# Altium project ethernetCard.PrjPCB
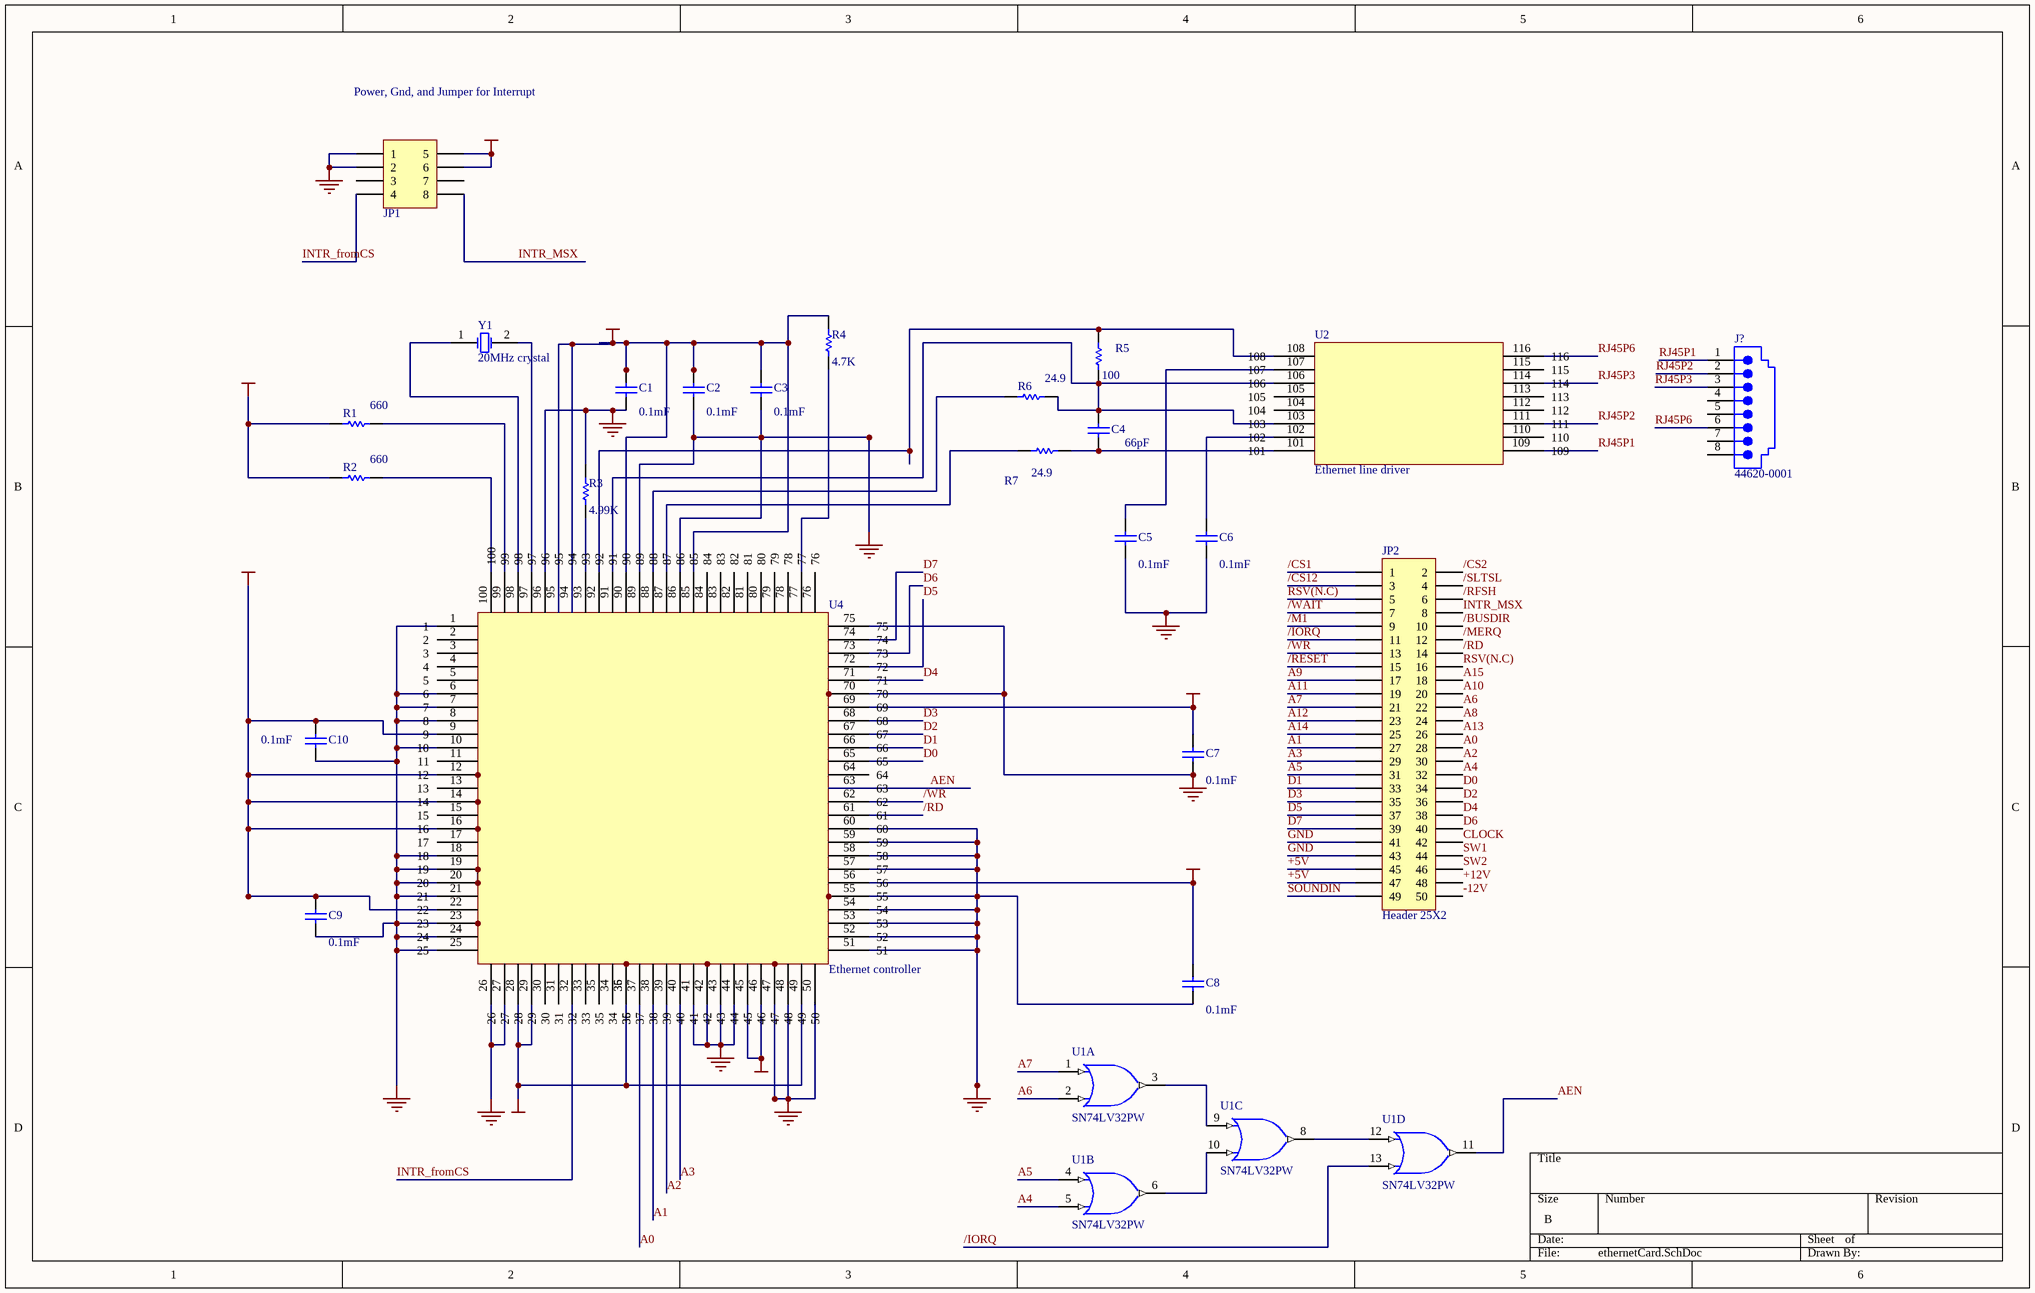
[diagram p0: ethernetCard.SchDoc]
1 sheet, 24 parts. Net scope: global (net labels, ports and power ports of the same name join across sheets).

## Sheet ethernetCard.SchDoc: Ethernet Card for the MSX computer
size B; Author: David Regal and Bruno Barreyra

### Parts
C1  value 0.1mF  [RAD-0.3]  (hidden comment: Cap)
C2  value 0.1mF  [RAD-0.3]  (hidden comment: Cap)
C3  value 0.1mF  [RAD-0.3]  (hidden comment: Cap)
C4  value 66pF  [RAD-0.3]  (hidden comment: Cap)
C5  value 0.1mF  [RAD-0.3]  (hidden comment: Cap)
C6  value 0.1mF  [RAD-0.3]  (hidden comment: Cap)
C7  value 0.1mF  [RAD-0.3]  (hidden comment: Cap)
C8  value 0.1mF  [RAD-0.3]  (hidden comment: Cap)
C9  value 0.1mF  [RAD-0.3]
C10  value 0.1mF  [RAD-0.3]  (hidden comment: Cap)
J?  44620-0001  [JACK1.02-2H8E]
JP1  Power, Gnd, and Jumper for Interrupt  [HDR2X4_CEN]
JP2  Header 25X2  [HDR2X25]
R1  value 660  [AXIAL-0.3]  (hidden comment: 660 ohm)
R2  value 660  [AXIAL-0.3]  (hidden comment: Res1)
R3  value 4.99K  [AXIAL-0.3]  (hidden comment: Res1)
R4  value 4.7K  [AXIAL-0.3]
R5  value 100  [AXIAL-0.3]
R6  value 24.9  [AXIAL-0.3]  (hidden comment: Res1)
R7  value 24.9  [AXIAL-0.3]  (hidden comment: Res1)
U1  SN74LV32PW  [TSSO5x6-G14/X.3]  (parts A,B,C,D of 4)
U2  Ethernet line driver
U4  Ethernet controller  [Model Name]
Y1  20MHz crystal  [BCY-W2/D3.1]

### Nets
GND: C1.1 C2.1 C3.1 C5.1 C6.1 C7.1 C8.1 C9.2 C10.1 JP1.1 JP1.2 JP2.41 JP2.43 R3.2 U4.1 U4.6 U4.7 U4.8 U4.10 U4.18 U4.19 U4.20 U4.21 U4.23 U4.24 U4.25 U4.26 U4.27 U4.41 U4.42 U4.43 U4.44 U4.47 U4.48 U4.50 U4.51 U4.52 U4.53 U4.54 U4.55 U4.57 U4.58 U4.59 U4.60 U4.70 U4.75 U4.86 U4.89 U4.96
VCC: C1.2 C2.2 C3.2 C7.2 C8.2 C9.1 C10.2 JP1.5 JP1.6 R1.2 R2.2 R4.2 U4.9 U4.12 U4.14 U4.16 U4.22 U4.28 U4.29 U4.35 U4.36 U4.45 U4.46 U4.49 U4.56 U4.69 U4.85 U4.90
+5V: JP2.45 JP2.47
+12V: JP2.48
-12V: JP2.50
/BUSDIR: JP2.10
/CS1: JP2.1
/CS2: JP2.2
/CS12: JP2.3
/IORQ: JP2.11 U1.13(B)
/M1: JP2.9
/MERQ: JP2.12
/RD: JP2.14 U4.61
/RESET: JP2.15
/RFSH: JP2.6
/SLTSL: JP2.4
/WAIT: JP2.7
/WR: JP2.13 U4.62
A0: JP2.28 U4.37
A1: JP2.27 U4.38
A2: JP2.30 U4.39
A3: JP2.29 U4.40
A4: JP2.32 U1.5(B)
A5: JP2.31 U1.4(A)
A6: JP2.22 U1.2(B)
A7: JP2.21 U1.1(A)
A8: JP2.24
A9: JP2.17
A10: JP2.20
A11: JP2.19
A12: JP2.23
A13: JP2.26
A14: JP2.25
A15: JP2.18
AEN: U1.11(Y) U4.63
CLOCK: JP2.42
D0: JP2.34 U4.65
D1: JP2.33 U4.66
D2: JP2.36 U4.67
D3: JP2.35 U4.68
D4: JP2.38 U4.71
D5: JP2.37 U4.72
D6: JP2.40 U4.73
D7: JP2.39 U4.74
INTR_fromCS: JP1.4 U4.32
INTR_MSX: JP1.8 JP2.8
RJ45P1: J?.1 U2.109
RJ45P2: J?.2 U2.111
RJ45P3: J?.3 U2.114
RJ45P6: J?.6 U2.116
RSV(N.C): JP2.5 JP2.16
SOUNDIN: JP2.49
SW1: JP2.44
SW2: JP2.46
NetC4_1: C4.1 R7.1 U2.101
NetC4_2: C4.2 R5.1 R6.2 U2.103 U2.106 U4.91
NetC5_2: C5.2 U2.107
NetC6_2: C6.2 U2.102
NetR1_1: R1.1 U4.99
NetR2_1: R2.1 U4.100
NetR3_1: R3.1 U4.93
NetR4_1: R4.1 U4.77
NetR5_2: R5.2 U2.108 U4.92
NetR6_1: R6.1 U4.88
NetR7_2: R7.2 U4.87
NetU1_3: U1.3(Y) U1.9(A)
NetU1_6: U1.6(Y) U1.10(B)
NetU1_8: U1.8(Y) U1.12(A)
NetU4_94: U4.94 U4.95
NetU4_97: U4.97 Y1.2(OSC2)
NetU4_98: U4.98 Y1.1(OSC1)

Not connected (* = marked no-connect by the designer): J? 4 5 7 8; JP1 3 7; U1 7(GND) 14(VCC); U2 104 105 110 112 113 115; U4 2 3 4 5 11 13 15 17 30 31 33 34 64 76 78 79 80 81 82 83 84

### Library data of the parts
C1-C10 = Cap: Capacitor; Manufacturer: Generic Components; Class: Passive
J? = 44620-0001: Modular Jack , Right Angle RJ-45, Low Profile, Inverted, Unshielded with RJ-11 Keepout Feature; Manufacturer: Molex; Package Information: Latest Revision: 18-Apr-2001; Class I: Connector; Class II: Modular Jacks; Ports: 1; Positions/Loaded: Port1: 8/8; PCB Mounting: THT; Drill Diameter: Nominal, Rounded to nearest 0.05mm; PCB Layout: Complies with Manufacturer's Recommendation.
JP1 = Header 4X2A: Header, 4-Pin, Dual row; Manufacturer: Generic Components; Class: Connector
JP2 = Header 25X2: Header, 25-Pin, Dual row; Manufacturer: Generic Components; Class: Connector
R1-R7 = Res1: Resistor; Manufacturer: Generic Components; Class: Passive
U1 = SN74LV32PW: Quadruple 2-Input Positive-OR Gate; Manufacturer: Texas Instruments; Class: Logic
U2 = HALO: Changes voltages
U4 = CS8900: Chip for controlling ethernet communication
Y1 = XTAL: Crystal Oscillator; Manufacturer: Generic Components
